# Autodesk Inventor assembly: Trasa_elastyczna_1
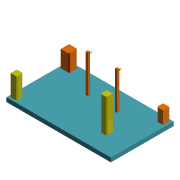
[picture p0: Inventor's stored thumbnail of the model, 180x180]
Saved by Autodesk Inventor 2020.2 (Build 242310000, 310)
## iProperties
Created: 2014-08
Part Number: Trasa_elastyczna_1
Document SubType Name: Assembly
Designer: F.Stasiak
Catalog Web Link: www.expertbooks.pl
Manager: www.cadconsulting.pl
Company: Fabian Stasiak CAD Consulting
Author: F.Stasiak
Subject: Zbiór ćwiczeń. Autodesk Inventor 2020. Kurs Professional
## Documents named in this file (2)
- C:\2020_Kurs_Professional\R1 Rury\Trasa_elastyczna_1.iam
- C:\2020_Kurs_Professional\R1 Rury\Konstrukcja_elastyczna_1.ipt
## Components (1 placed, 1 different names)
1. Konstrukcja_elastyczna_1:1
